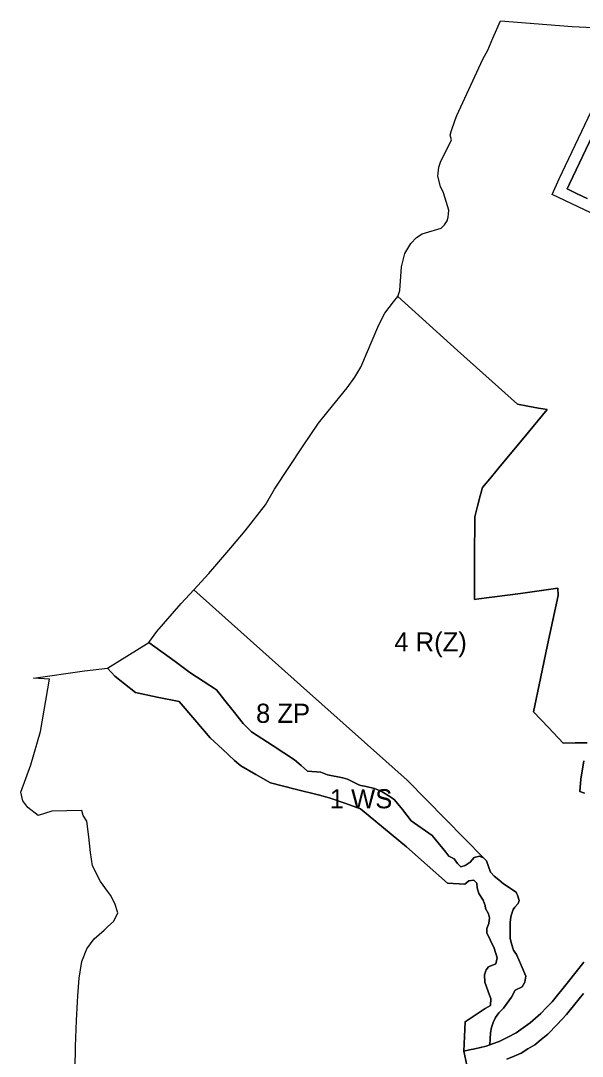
# Model space of a CAD drawing. Extents: x -294445 to -292055, y 21869 to 23693.
# Drawn here: x -294445 to -294152, y 22472 to 23013 of the extents above; entities that cross this region are included whole.
import ezdxf

# ---------------------------------------------------------------- set-up
doc = ezdxf.new("R2010")
doc.units = 0
for name, color, linetype in [('linie_rozgraniczajace', 7, 'Continuous'), ('linie_zabudowy_nieprzekraczalne', 7, 'Continuous'), ('oznaczenia_przeznaczen', 7, 'Continuous')]:
    doc.layers.add(name, color=color, linetype=linetype)

msp = doc.modelspace()

# ---------------------------------------------------------------- linework, layer by layer
at = {"layer": 'linie_rozgraniczajace'}
for points in [[(-294248.36, 22868.75), (-294247.17, 22871.85), (-294246.35, 22884.29), (-294244.62, 22891.24), (-294241.51, 22896.39), (-294238.58, 22899.64), (-294235.54, 22901.49), (-294225.63, 22904.4), (-294223.98, 22906.24), (-294222.55, 22908.24), (-294222.02, 22910.29), (-294221.85, 22911.9), (-294221.57, 22913.93), (-294224.48, 22922.89), (-294226.02, 22926.2), (-294227.33, 22931.63), (-294226.93, 22936.3), (-294226.05, 22938.97), (-294220.29, 22950.67), (-294220.92, 22953.02), (-294220.48, 22955.09), (-294218.27, 22961.09), (-294217.51, 22963.38), (-294203.84, 22992.77), (-294201.34, 22997.51), (-294198.66, 23003.75), (-294194.71, 23012.94), (-294157.15, 23009.86), (-294138.732, 23009.066)], [(-294144.84, 22956.635), (-294158.61, 22927.73), (-294159.813, 22924.999), (-294154.577, 22922.459), (-294149.34, 22919.92)], [(-294159.813, 22924.999), (-294158.61, 22927.73), (-294144.84, 22956.635)], [(-294149.34, 22919.92), (-294154.577, 22922.459), (-294159.813, 22924.999)], [(-294354.965, 22715.392), (-294347.1, 22724.03), (-294335.48, 22737.33), (-294328.03, 22746.18), (-294317.49, 22759.91), (-294312.71, 22768.12), (-294297.75, 22790.61), (-294289.72, 22802.53), (-294284.77, 22808.81), (-294274.84, 22820.94), (-294270.71, 22826.57), (-294267.65, 22831.79), (-294258.2, 22853.98), (-294255.06, 22860.09), (-294250.64, 22865.97), (-294248.36, 22868.75), (-294217.095, 22840.57), (-294185.83, 22812.39), (-294180.307, 22811.424), (-294174.783, 22810.457), (-294170.17, 22809.65), (-294182.47, 22794.86), (-294194.77, 22780.07), (-294199.4, 22774.505), (-294204.03, 22768.94), (-294205.19, 22764.59), (-294206.66, 22759.115), (-294208.13, 22753.64), (-294208.205, 22731.98), (-294208.28, 22710.32), (-294206.04, 22710.62), (-294184.205, 22713.564), (-294164.611, 22716.209), (-294164.48, 22712.42), (-294167.282, 22699.518), (-294170.083, 22686.616), (-294173.721, 22669.085), (-294177.359, 22651.555), (-294169.62, 22643.417), (-294161.88, 22635.28), (-294155.605, 22635.36), (-294149.33, 22635.44)], [(-294149.33, 22635.44), (-294155.605, 22635.36), (-294161.88, 22635.28), (-294169.62, 22643.417), (-294177.359, 22651.555), (-294173.721, 22669.085), (-294170.083, 22686.616), (-294167.282, 22699.518), (-294164.48, 22712.42), (-294164.611, 22716.209), (-294184.205, 22713.564), (-294206.04, 22710.62), (-294208.28, 22710.32), (-294208.205, 22731.98), (-294208.13, 22753.64), (-294206.66, 22759.115), (-294205.19, 22764.59), (-294204.03, 22768.94), (-294199.4, 22774.505), (-294194.77, 22780.07), (-294182.47, 22794.86), (-294170.17, 22809.65), (-294174.783, 22810.457), (-294180.307, 22811.424), (-294185.83, 22812.39), (-294217.095, 22840.57), (-294248.36, 22868.75)], [(-294185.58, 22555.18), (-294185.81, 22555.795), (-294186.04, 22556.41), (-294186.47, 22557.29), (-294187.83, 22558.22), (-294191.08, 22560.45), (-294192.987, 22561.762), (-294195.48, 22563.75), (-294197.99, 22565.75), (-294199.92, 22567.78), (-294200.92, 22570.765), (-294201.92, 22573.75), (-294203.5, 22575.36), (-294223.465, 22595.59), (-294243.43, 22615.82), (-294299.198, 22665.606), (-294354.965, 22715.392)], [(-294400, 22674.49), (-294378.391, 22687.8), (-294378.39, 22687.8), (-294364.59, 22678.02), (-294356.9, 22672.13), (-294349.975, 22667.645), (-294343.05, 22663.16), (-294338.685, 22657.635), (-294334.32, 22652.11), (-294329.06, 22645.5), (-294324.74, 22641.09), (-294313.485, 22633.83), (-294302.23, 22626.57), (-294298.835, 22623.61), (-294295.44, 22620.65), (-294288.6, 22620.16), (-294285.06, 22618.65), (-294277.11, 22617.19), (-294274.54, 22616.37), (-294271.502, 22614.816), (-294269.73, 22613.91), (-294268.68, 22613.535), (-294267.63, 22613.16), (-294264.86, 22612.63), (-294260.45, 22611.52), (-294257.07, 22610.17), (-294251.87, 22607), (-294250.08, 22605.55), (-294245.84, 22600.56), (-294241.31, 22594.59), (-294230.39, 22586.93), (-294223.14, 22578.21), (-294221.57, 22576.19), (-294218.87, 22574.78), (-294217.18, 22572.36), (-294215.42, 22570.68), (-294213.02, 22571.27), (-294210.44, 22573.09), (-294208.4, 22575.46), (-294205.68, 22576.21), (-294203.5, 22575.36), (-294201.92, 22573.75), (-294200.92, 22570.765), (-294199.92, 22567.78), (-294197.99, 22565.75), (-294195.48, 22563.75), (-294192.987, 22561.762), (-294191.08, 22560.45), (-294187.83, 22558.22), (-294186.47, 22557.29), (-294186.04, 22556.41), (-294185.81, 22555.795), (-294185.58, 22555.18), (-294184.93, 22552.92), (-294185.42, 22551.43), (-294187.19, 22549.56), (-294187.98, 22548.23), (-294188.53, 22546.655), (-294189.08, 22545.08), (-294189.36, 22543.16), (-294189.64, 22541.24), (-294189.585, 22537.285), (-294189.53, 22533.33), (-294188.91, 22530.32), (-294187.82, 22527.02), (-294187.08, 22525.91), (-294186.34, 22524.8), (-294183.85, 22519.115), (-294181.35, 22513.427), (-294181.99, 22510.3), (-294183.32, 22507.78), (-294187.04, 22506.06), (-294188.9, 22502.48), (-294193, 22496.66), (-294195.47, 22494.25), (-294197.24, 22491.83), (-294198.48, 22489.2), (-294199.4, 22486.55), (-294199.94, 22483.77), (-294200.229, 22477.519), (-294202.195, 22476.831), (-294205.087, 22476.108), (-294207.98, 22475.386), (-294210.848, 22474.846), (-294213.715, 22474.306), (-294213.12, 22489.65), (-294202.7, 22496.57), (-294199.93, 22498.15), (-294199.66, 22501.73), (-294200.42, 22503.58), (-294202.89, 22510.22), (-294202.94, 22514.11), (-294202.21, 22516.81), (-294200.98, 22518.39), (-294197.15, 22519.85), (-294196.46, 22522.98), (-294197.94, 22528.08), (-294201.78, 22536.12), (-294201.7, 22538.3), (-294200.66, 22541.05)], [(-294445.36, 22609.65), (-294440.04, 22623.86), (-294434.96, 22641.41), (-294430.3, 22668.77), (-294438.69, 22669.18), (-294411.97, 22673.03), (-294400, 22674.49), (-294396.23, 22670.35), (-294391.21, 22666.27), (-294385.46, 22661.7), (-294374.01, 22659.35), (-294362.56, 22657), (-294354.425, 22647.49), (-294346.29, 22637.98), (-294339.94, 22632.075), (-294333.59, 22626.17), (-294330.27, 22623.48), (-294322.535, 22618.955), (-294314.8, 22614.43), (-294301.99, 22611.26), (-294289.18, 22608.09), (-294284.13, 22606.69), (-294275.99, 22603.81), (-294267.85, 22600.93), (-294255.81, 22591), (-294243.77, 22581.07), (-294233.015, 22571.55), (-294222.26, 22562.03), (-294213.36, 22561.5), (-294211.19, 22563.24), (-294208.65, 22563.65), (-294207, 22562.07), (-294206.75, 22559.64), (-294205.88, 22556.67), (-294203.7, 22553.24), (-294202.69, 22550.45), (-294202.44, 22548.8), (-294200.87, 22546.03), (-294200.38, 22543.89), (-294200.66, 22541.05), (-294201.7, 22538.3), (-294201.78, 22536.12), (-294197.94, 22528.08), (-294196.46, 22522.98), (-294197.15, 22519.85), (-294200.98, 22518.39), (-294202.21, 22516.81), (-294202.94, 22514.11), (-294202.89, 22510.22), (-294200.42, 22503.58), (-294199.66, 22501.73), (-294199.93, 22498.15), (-294202.7, 22496.57), (-294213.12, 22489.65), (-294213.715, 22474.306), (-294211.668, 22464.48)], [(-294200.66, 22541.05), (-294200.38, 22543.89), (-294200.87, 22546.03), (-294202.44, 22548.8), (-294202.69, 22550.45), (-294203.7, 22553.24), (-294205.88, 22556.67), (-294206.75, 22559.64), (-294207, 22562.07), (-294208.65, 22563.65), (-294211.19, 22563.24), (-294213.36, 22561.5), (-294222.26, 22562.03), (-294233.015, 22571.55), (-294243.77, 22581.07), (-294255.81, 22591), (-294267.85, 22600.93), (-294275.99, 22603.81), (-294284.13, 22606.69), (-294289.18, 22608.09), (-294301.99, 22611.26), (-294314.8, 22614.43), (-294322.535, 22618.955), (-294330.27, 22623.48), (-294333.59, 22626.17), (-294339.94, 22632.075), (-294346.29, 22637.98), (-294354.425, 22647.49), (-294362.56, 22657), (-294374.01, 22659.35), (-294385.46, 22661.7), (-294391.21, 22666.27), (-294396.23, 22670.35), (-294400, 22674.49)], [(-294150.72, 22609.19), (-294153.17, 22609.97), (-294152.71, 22616.49), (-294151.02, 22625.965)], [(-294151.02, 22625.965), (-294152.71, 22616.49), (-294153.17, 22609.97), (-294150.72, 22609.19)], [(-294416.83, 22465.07), (-294416.79, 22476.66), (-294416.22, 22490.24), (-294415.66, 22500), (-294415.47, 22503.22), (-294414.74, 22512.44), (-294413.35, 22521.19), (-294410.89, 22527.76), (-294407.02, 22532.92), (-294401.79, 22537.53), (-294400, 22539.17), (-294396.75, 22542.15), (-294394.69, 22546.52), (-294396.13, 22551.45), (-294398.48, 22555.78), (-294400, 22557.85), (-294403.75, 22562.94), (-294407.89, 22571.08), (-294408.91, 22578.07), (-294409.68, 22586.35), (-294410.87, 22594.44), (-294412.81, 22597.44), (-294413.41, 22600.06), (-294429.02, 22599.74), (-294436.23, 22597.41), (-294441.71, 22601.63), (-294444.25, 22605.04), (-294445.36, 22609.65)], [(-294151.168, 22520.795), (-294159.072, 22510.604), (-294167.698, 22500), (-294170.61, 22497), (-294173.522, 22494), (-294176.312, 22491.53), (-294179.102, 22489.061), (-294182.786, 22486.429), (-294186.471, 22483.797), (-294190.885, 22481.521), (-294195.298, 22479.245), (-294198.746, 22478.038), (-294200.229, 22477.519), (-294199.94, 22483.77), (-294199.4, 22486.55), (-294198.48, 22489.2), (-294197.24, 22491.83), (-294195.47, 22494.25), (-294193, 22496.66), (-294188.9, 22502.48), (-294187.04, 22506.06), (-294183.32, 22507.78), (-294181.99, 22510.3), (-294181.35, 22513.427), (-294183.85, 22519.115), (-294186.34, 22524.8), (-294187.08, 22525.91), (-294187.82, 22527.02), (-294188.91, 22530.32), (-294189.53, 22533.33), (-294189.585, 22537.285), (-294189.64, 22541.24), (-294189.36, 22543.16), (-294189.08, 22545.08), (-294188.53, 22546.655), (-294187.98, 22548.23), (-294187.19, 22549.56), (-294185.42, 22551.43), (-294184.93, 22552.92), (-294185.58, 22555.18)], [(-294213.715, 22474.306), (-294210.848, 22474.846), (-294207.98, 22475.386), (-294205.087, 22476.108), (-294202.195, 22476.831), (-294200.229, 22477.519), (-294198.746, 22478.038), (-294195.298, 22479.245), (-294190.885, 22481.521), (-294186.471, 22483.797), (-294182.786, 22486.429), (-294179.102, 22489.061), (-294176.312, 22491.53), (-294173.522, 22494), (-294170.61, 22497), (-294167.698, 22500), (-294159.072, 22510.604), (-294151.168, 22520.795)], [(-294191.335, 22470.037), (-294187.571, 22471.638), (-294183.807, 22473.239), (-294180.294, 22475.397), (-294176.781, 22477.555), (-294173.384, 22480.329), (-294169.988, 22483.103), (-294165.102, 22488.227), (-294160.217, 22493.35), (-294155.766, 22498.821), (-294151.315, 22504.293)], [(-294151.315, 22504.293), (-294155.766, 22498.821), (-294160.217, 22493.35), (-294165.102, 22488.227), (-294169.988, 22483.103), (-294173.384, 22480.329), (-294176.781, 22477.555), (-294180.294, 22475.397), (-294183.807, 22473.239), (-294187.571, 22471.638), (-294191.335, 22470.037)], [(-294211.668, 22464.48), (-294213.715, 22474.306)]]:
    msp.add_lwpolyline(points, dxfattribs=at)
msp.add_lwpolyline([(-294378.39, 22687.8), (-294374.31, 22693.68), (-294361.44, 22708.28), (-294354.965, 22715.392), (-294299.198, 22665.606), (-294243.43, 22615.82), (-294223.465, 22595.59), (-294203.5, 22575.36), (-294205.68, 22576.21), (-294208.4, 22575.46), (-294210.44, 22573.09), (-294213.02, 22571.27), (-294215.42, 22570.68), (-294217.18, 22572.36), (-294218.87, 22574.78), (-294221.57, 22576.19), (-294223.14, 22578.21), (-294230.39, 22586.93), (-294241.31, 22594.59), (-294245.84, 22600.56), (-294250.08, 22605.55), (-294251.87, 22607), (-294257.07, 22610.17), (-294260.45, 22611.52), (-294264.86, 22612.63), (-294267.63, 22613.16), (-294268.68, 22613.535), (-294269.73, 22613.91), (-294271.502, 22614.816), (-294274.54, 22616.37), (-294277.11, 22617.19), (-294285.06, 22618.65), (-294288.6, 22620.16), (-294295.44, 22620.65), (-294298.835, 22623.61), (-294302.23, 22626.57), (-294313.485, 22633.83), (-294324.74, 22641.09), (-294329.06, 22645.5), (-294334.32, 22652.11), (-294338.685, 22657.635), (-294343.05, 22663.16), (-294349.975, 22667.645), (-294356.9, 22672.13), (-294364.59, 22678.02)], close=True, dxfattribs=at)
at = {"layer": 'linie_zabudowy_nieprzekraczalne'}
msp.add_lwpolyline([(-294140.507, 22909.16), (-294167.636, 22922.124), (-294164.065, 22930.23), (-294135.378, 22990.357)], dxfattribs=at)

# ---------------------------------------------------------------- texts
at = {"layer": 'oznaczenia_przeznaczen'}
for s, p in [('4 R(Z)', (-294250.121, 22683.18)), ('8 ZP', (-294322.4, 22645.877)), ('1 WS', (-294283.876, 22601.2))]:
    msp.add_text(s, height=10, dxfattribs=at).set_placement(p)

doc.saveas('drawing.dxf')
